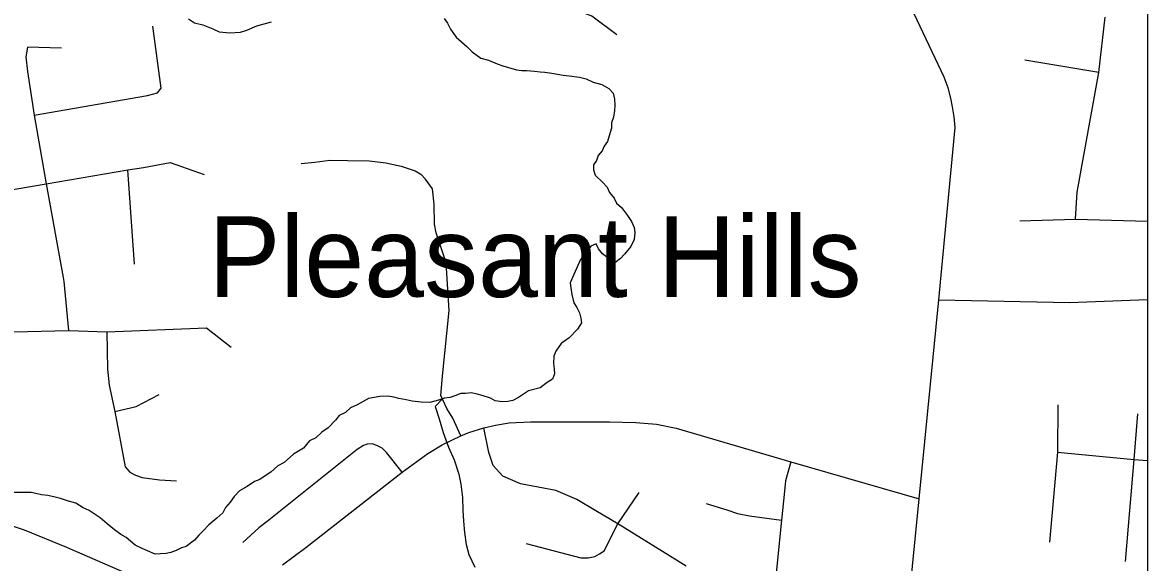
# Model space of a CAD drawing. Extents: x 0 to 69.5, y -4.5 to 22.
# Drawn here: x 7.698 to 8.8, y 16.203 to 16.732 of the extents above; entities that cross this region are included whole.
import ezdxf

# ---------------------------------------------------------------- set-up
doc = ezdxf.new("R2010")
doc.units = 0
for name, color, linetype in [('GM_X_County_Road', 7, 'Continuous'), ('GM_X_Minor_River', 7, 'Continuous'), ('GM_X_Township_Subdivision', 7, 'Continuous'), ('GM_X_Unincorporated_Text', 7, 'Continuous'), ('SH_Data', 7, 'Continuous')]:
    doc.layers.add(name, color=color, linetype=linetype)

msp = doc.modelspace()

# ---------------------------------------------------------------- linework, layer by layer
at = {"layer": 'GM_X_County_Road'}
for points in [[(8.54, 16.0139), (8.547, 16.039), (8.5505, 16.0505), (8.5551, 16.0697), (8.5597, 16.0973), (8.5763, 16.2655), (8.5957, 16.4605), (8.6116, 16.6291), (8.6107, 16.6398), (8.609, 16.6494), (8.6074, 16.6579), (8.6047, 16.6681), (8.6008, 16.6786), (8.5656, 16.7531)], [(8.5957, 16.4605), (8.7235, 16.4578), (8.8, 16.4607)], [(7.9527, 16.2007), (7.9755, 16.2178), (8.0699, 16.2915), (8.0949, 16.3097), (8.109, 16.3183), (8.1273, 16.3271), (8.1352, 16.3304), (8.15, 16.335), (8.1613, 16.3376), (8.1746, 16.3398), (8.1955, 16.3408), (8.2731, 16.3408), (8.2986, 16.3403), (8.319, 16.3385), (8.3384, 16.3346), (8.4505, 16.3018), (8.5763, 16.2655)], [(7.6849, 16.2399), (7.6994, 16.2351), (7.7409, 16.218), (7.7987, 16.1928)]]:
    msp.add_lwpolyline(points, dxfattribs=at)
at = {"layer": 'GM_X_Minor_River'}
for points in [[(7.8604, 16.7358), (7.8664, 16.7318), (7.8747, 16.7297), (7.8845, 16.726), (7.8905, 16.7231), (7.9011, 16.7221), (7.9114, 16.7226), (7.9175, 16.7247), (7.9275, 16.729), (7.9417, 16.7327)], [(8.111, 16.736), (8.1143, 16.7313), (8.1172, 16.7256), (8.1227, 16.7178), (8.1331, 16.7087), (8.1383, 16.7033), (8.1468, 16.6973), (8.1544, 16.6952), (8.163, 16.6915), (8.1683, 16.6895), (8.1819, 16.6857), (8.1872, 16.6851), (8.1918, 16.685), (8.1994, 16.6844), (8.205, 16.6839), (8.2096, 16.6834), (8.2164, 16.6824), (8.2221, 16.6815), (8.2274, 16.6806), (8.2335, 16.68), (8.2437, 16.6786), (8.2501, 16.6769), (8.2569, 16.6737), (8.2656, 16.6715), (8.2723, 16.6675), (8.2767, 16.6628), (8.2777, 16.6571), (8.2783, 16.651), (8.2778, 16.646), (8.2768, 16.6392), (8.2748, 16.6339), (8.275, 16.6286), (8.2725, 16.6211), (8.2709, 16.6154), (8.2677, 16.6109), (8.2657, 16.6064), (8.2618, 16.6019), (8.2601, 16.597)], [(8.2601, 16.597), (8.2573, 16.5925), (8.2572, 16.5876), (8.259, 16.5826), (8.2664, 16.5752), (8.2708, 16.5708), (8.2729, 16.5654), (8.2774, 16.56), (8.2799, 16.555), (8.2847, 16.551), (8.2906, 16.5429), (8.2946, 16.537), (8.2971, 16.5313), (8.2977, 16.5263), (8.2972, 16.5195), (8.2939, 16.5127), (8.2877, 16.5052), (8.2837, 16.5008), (8.2783, 16.4967), (8.2731, 16.5003), (8.266, 16.5055), (8.2623, 16.5105), (8.2598, 16.5152), (8.2548, 16.513), (8.25, 16.5063), (8.2445, 16.5), (8.2381, 16.4853), (8.2344, 16.477), (8.235, 16.4721), (8.236, 16.4656), (8.2381, 16.4575), (8.241, 16.4529), (8.2435, 16.4475), (8.2449, 16.4425), (8.2455, 16.4379), (8.2415, 16.4315), (8.2333, 16.423), (8.2256, 16.4175), (8.2204, 16.41), (8.2184, 16.4051), (8.2182, 16.3979), (8.2188, 16.3929), (8.2191, 16.388), (8.217, 16.3827), (8.212, 16.3794), (8.205, 16.3743), (8.1935, 16.3712), (8.1838, 16.3646), (8.1784, 16.3617), (8.1735, 16.3607), (8.1677, 16.3605), (8.1609, 16.3614), (8.1564, 16.3642), (8.1481, 16.3667), (8.1432, 16.368), (8.1376, 16.3693), (8.1318, 16.3687), (8.1273, 16.3685), (8.1215, 16.3663), (8.1169, 16.3646), (8.1112, 16.364), (8.1054, 16.3622), (8.097, 16.3598), (8.0883, 16.36), (8.0795, 16.361), (8.0739, 16.3623), (8.0667, 16.3637), (8.0618, 16.365), (8.0557, 16.3659), (8.0481, 16.3657), (8.037, 16.3637), (8.0258, 16.3576), (8.0193, 16.3547), (8.0142, 16.3499), (8.008, 16.347), (8.0045, 16.3426), (7.9974, 16.3351), (7.9912, 16.3307), (7.9854, 16.3252), (7.9792, 16.3223), (7.9733, 16.3149), (7.9683, 16.312), (7.9633, 16.3091), (7.9543, 16.3009), (7.9481, 16.2977), (7.9411, 16.2914), (7.9357, 16.2881), (7.9303, 16.2845), (7.9253, 16.2823), (7.9179, 16.2776), (7.9106, 16.2732), (7.9051, 16.2677), (7.9012, 16.2621), (7.8968, 16.2568), (7.894, 16.2516), (7.8882, 16.2464), (7.8804, 16.2398), (7.8749, 16.2342), (7.8706, 16.2298), (7.8663, 16.2249), (7.8581, 16.2187)], [(8.1092, 16.3634), (8.1022, 16.3558), (8.1061, 16.3439), (8.11, 16.3305), (8.1153, 16.3159), (8.1207, 16.3036), (8.1253, 16.2895), (8.1274, 16.2799), (8.1289, 16.2666), (8.1294, 16.2544), (8.1299, 16.2437), (8.1308, 16.2323), (8.1324, 16.2208), (8.1352, 16.2109), (8.141, 16.1986)], [(7.7063, 16.2717), (7.6879, 16.2716)], [(7.8581, 16.2187), (7.8535, 16.2173), (7.8485, 16.2148), (7.8432, 16.213), (7.8386, 16.212), (7.8332, 16.2114), (7.8279, 16.2112), (7.8204, 16.2144), (7.8151, 16.2169), (7.8084, 16.2201), (7.7994, 16.2276), (7.7942, 16.2304), (7.7879, 16.2351), (7.7808, 16.241), (7.7741, 16.2469), (7.7633, 16.2541), (7.7573, 16.2566), (7.7502, 16.2613), (7.743, 16.2631), (7.7351, 16.2659), (7.7298, 16.2672), (7.7226, 16.2686), (7.7165, 16.2695), (7.7109, 16.2708), (7.7063, 16.2717)]]:
    msp.add_lwpolyline(points, dxfattribs=at)
at = {"layer": 'GM_X_Township_Subdivision'}
for points in [[(8.1959, 16.8338), (8.1747, 16.7975), (8.1743, 16.7957), (8.174, 16.7932), (8.1742, 16.788), (8.1751, 16.7825), (8.1757, 16.7802), (8.1771, 16.7777), (8.1835, 16.7683), (8.1957, 16.76), (8.2556, 16.7386), (8.28, 16.7203)], [(8.7296, 16.5395), (8.7311, 16.5659), (8.7522, 16.683), (8.7585, 16.7373)], [(7.7093, 16.6414), (7.8203, 16.6605), (7.8303, 16.6631), (7.8338, 16.6678), (7.8255, 16.7285)], [(7.736, 16.7069), (7.7027, 16.708), (7.701, 16.6986), (7.7027, 16.6841), (7.7093, 16.6414), (7.7211, 16.5741), (7.7377, 16.4823)], [(8.7522, 16.683), (8.6797, 16.6953)], [(7.5407, 16.5266), (7.5754, 16.5245), (7.5942, 16.528), (7.6077, 16.5318), (7.6233, 16.5419), (7.6361, 16.5523), (7.6434, 16.5568), (7.6632, 16.5641), (7.7211, 16.5741), (7.8012, 16.5876), (7.8165, 16.5901), (7.8425, 16.5949), (7.8758, 16.5831)], [(7.8077, 16.4953), (7.8012, 16.5876)], [(7.9708, 16.5941), (7.9843, 16.5954), (7.999, 16.5971), (8.0164, 16.597), (8.0376, 16.5967), (8.0539, 16.5945), (8.0687, 16.5912), (8.0826, 16.5869), (8.0881, 16.5834), (8.0927, 16.5785)], [(8.1273, 16.3271), (8.1195, 16.3443), (8.1136, 16.354), (8.1078, 16.3666), (8.1092, 16.3855), (8.1158, 16.4501), (8.1129, 16.4965), (8.1033, 16.5259), (8.1016, 16.5346), (8.1013, 16.5541), (8.0996, 16.569), (8.0927, 16.5785)], [(8.675, 16.5377), (8.7296, 16.5395), (8.8, 16.5376)], [(7.7377, 16.4823), (7.7385, 16.4784), (7.743, 16.4302)], [(7.5312, 16.4263), (7.5571, 16.4253), (7.6223, 16.4274), (7.743, 16.4302), (7.7804, 16.4291), (7.8782, 16.4329), (7.9022, 16.4139)], [(7.7804, 16.4291), (7.7813, 16.3924), (7.7827, 16.3769), (7.7884, 16.3511), (7.7985, 16.2967), (7.8031, 16.2916), (7.8086, 16.2887), (7.8152, 16.2864), (7.8322, 16.2841), (7.8486, 16.2832)], [(7.7884, 16.3511), (7.8092, 16.356), (7.8318, 16.3678)], [(8.7122, 16.3576), (8.7119, 16.3113), (8.7041, 16.2229)], [(8.7784, 16.2041), (8.787, 16.304), (8.7906, 16.3486)], [(8.3479, 16.1995), (8.2811, 16.2409), (8.2596, 16.2537), (8.2409, 16.2647), (8.2204, 16.2736), (8.1856, 16.2801), (8.1684, 16.2875), (8.1589, 16.2982), (8.1548, 16.3109), (8.15, 16.335)], [(8.0699, 16.2915), (8.0546, 16.3109), (8.0504, 16.3152), (8.0451, 16.3178), (8.0403, 16.3192), (8.0356, 16.3189), (8.0318, 16.3176), (8.0259, 16.3137), (7.9375, 16.2432), (7.9295, 16.2371), (7.9138, 16.2226)], [(8.7119, 16.3113), (8.787, 16.304), (8.8, 16.3029)], [(8.4505, 16.3018), (8.4455, 16.283), (8.4443, 16.2728), (8.4414, 16.2444), (8.4278, 16.1081)], [(8.1913, 16.2217), (8.245, 16.2076), (8.2521, 16.2076), (8.2586, 16.2089), (8.2633, 16.2115), (8.2678, 16.2144), (8.2811, 16.2409), (8.302, 16.2717)], [(8.3675, 16.2608), (8.3878, 16.2546), (8.3984, 16.251), (8.41, 16.2487), (8.4414, 16.2444)]]:
    msp.add_lwpolyline(points, dxfattribs=at)
at = {"layer": 'SH_Data'}
msp.add_line((8.8, 21), (8.8, 14.2), dxfattribs=at)

# ---------------------------------------------------------------- texts
at = {"layer": 'GM_X_Unincorporated_Text'}
msp.add_text('Pleasant Hills', height=0.078977, rotation=0, dxfattribs=at).set_placement((7.88, 16.4632))

doc.saveas('drawing.dxf')
